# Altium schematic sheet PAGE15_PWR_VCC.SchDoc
size 381 x 381 mm; SheetNumber: 16; SheetTotal: 28
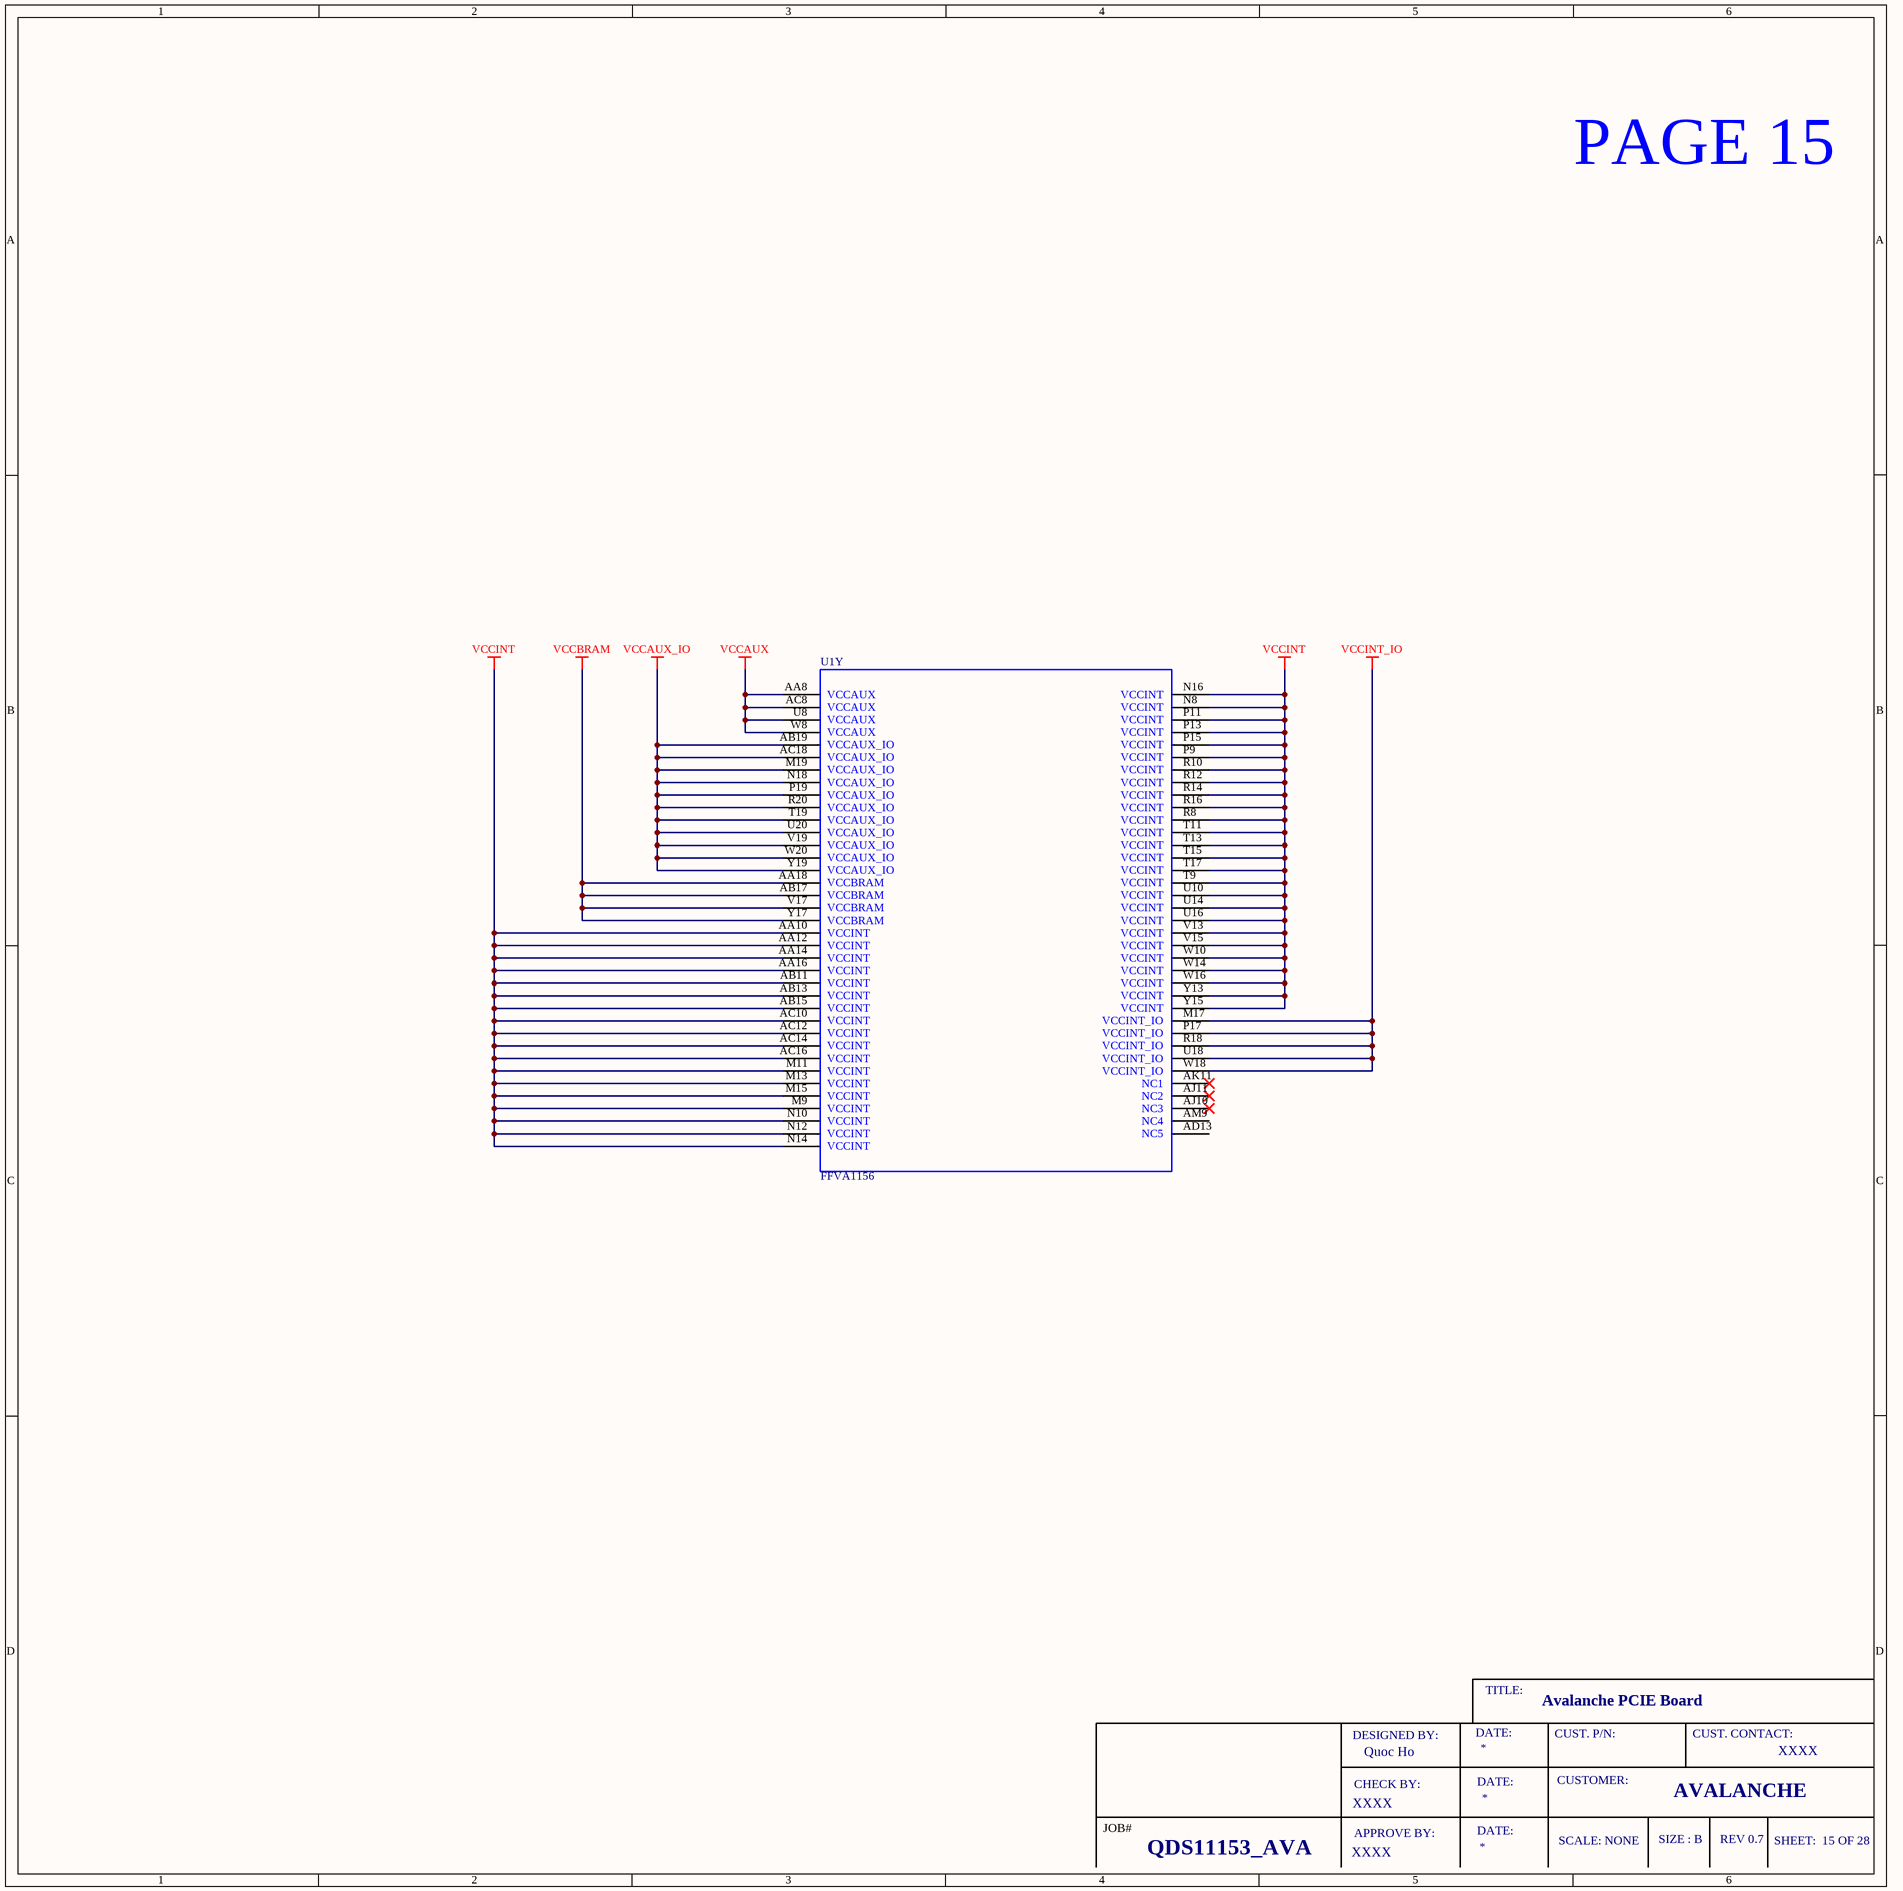
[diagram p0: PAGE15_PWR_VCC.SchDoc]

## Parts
U1  FFVA1156  [FFVA1156]  (part Y of 25)

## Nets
VCCAUX: U1.AA8(VCCAUX) U1.AC8(VCCAUX) U1.U8(VCCAUX) U1.W8(VCCAUX)
VCCAUX_IO: U1.AB19(VCCAUX_IO) U1.AC18(VCCAUX_IO) U1.M19(VCCAUX_IO) U1.N18(VCCAUX_IO) U1.P19(VCCAUX_IO) U1.R20(VCCAUX_IO) U1.T19(VCCAUX_IO) U1.U20(VCCAUX_IO) U1.V19(VCCAUX_IO) U1.W20(VCCAUX_IO) U1.Y19(VCCAUX_IO)
VCCBRAM: U1.AA18(VCCBRAM) U1.AB17(VCCBRAM) U1.V17(VCCBRAM) U1.Y17(VCCBRAM)
VCCINT: U1.AA10(VCCINT) U1.AA12(VCCINT) U1.AA14(VCCINT) U1.AA16(VCCINT) U1.AB11(VCCINT) U1.AB13(VCCINT) U1.AB15(VCCINT) U1.AC10(VCCINT) U1.AC12(VCCINT) U1.AC14(VCCINT) U1.AC16(VCCINT) U1.M9(VCCINT) U1.M11(VCCINT) U1.M13(VCCINT) U1.M15(VCCINT) U1.N8(VCCINT) U1.N10(VCCINT) U1.N12(VCCINT) U1.N14(VCCINT) U1.N16(VCCINT) U1.P9(VCCINT) U1.P11(VCCINT) U1.P13(VCCINT) U1.P15(VCCINT) U1.R8(VCCINT) U1.R10(VCCINT) U1.R12(VCCINT) U1.R14(VCCINT) U1.R16(VCCINT) U1.T9(VCCINT) U1.T11(VCCINT) U1.T13(VCCINT) U1.T15(VCCINT) U1.T17(VCCINT) U1.U10(VCCINT) U1.U14(VCCINT) U1.U16(VCCINT) U1.V13(VCCINT) U1.V15(VCCINT) U1.W10(VCCINT) U1.W14(VCCINT) U1.W16(VCCINT) U1.Y13(VCCINT) U1.Y15(VCCINT)
VCCINT_IO: U1.M17(VCCINT_IO) U1.P17(VCCINT_IO) U1.R18(VCCINT_IO) U1.U18(VCCINT_IO) U1.W18(VCCINT_IO)

Not connected (* = marked no-connect by the designer): U1 AD13(NC5) AJ10(NC3)* AJ11(NC2)* AK11(NC1)* AM9(NC4)

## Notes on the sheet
- PAGE 15
- TITLE:
- Avalanche PCIE Board
- DESIGNED BY:
- CHECK BY:
- Quoc Ho
- DATE:
- CUST. P/N:
- CUSTOMER:
- CUST. CONTACT:
- XXXX
- JOB#
- APPROVE BY:
- SCALE: NONE
- SIZE : B
- AVALANCHE
- REV 0.7
- SHEET:  15 OF 28
- QDS11153_AVA

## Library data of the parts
U1 = FFVA1156: IC FPGA 516 I/O 1156FCBGA; Manufacturer: AMD; Manufacturer Part Number: XCKU15P-1FFVA1156E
